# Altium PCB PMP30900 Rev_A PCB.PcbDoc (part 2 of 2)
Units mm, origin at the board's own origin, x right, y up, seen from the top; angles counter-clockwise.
Board outline 88.9 x 46.99 mm, 6 copper layers (Top Layer, Layer 2, Layer 3, Layer 4, Layer 5, Bottom Layer), stack 1.76 mm thick; 101 components, 54 nets, 324 pads, 212 vias.
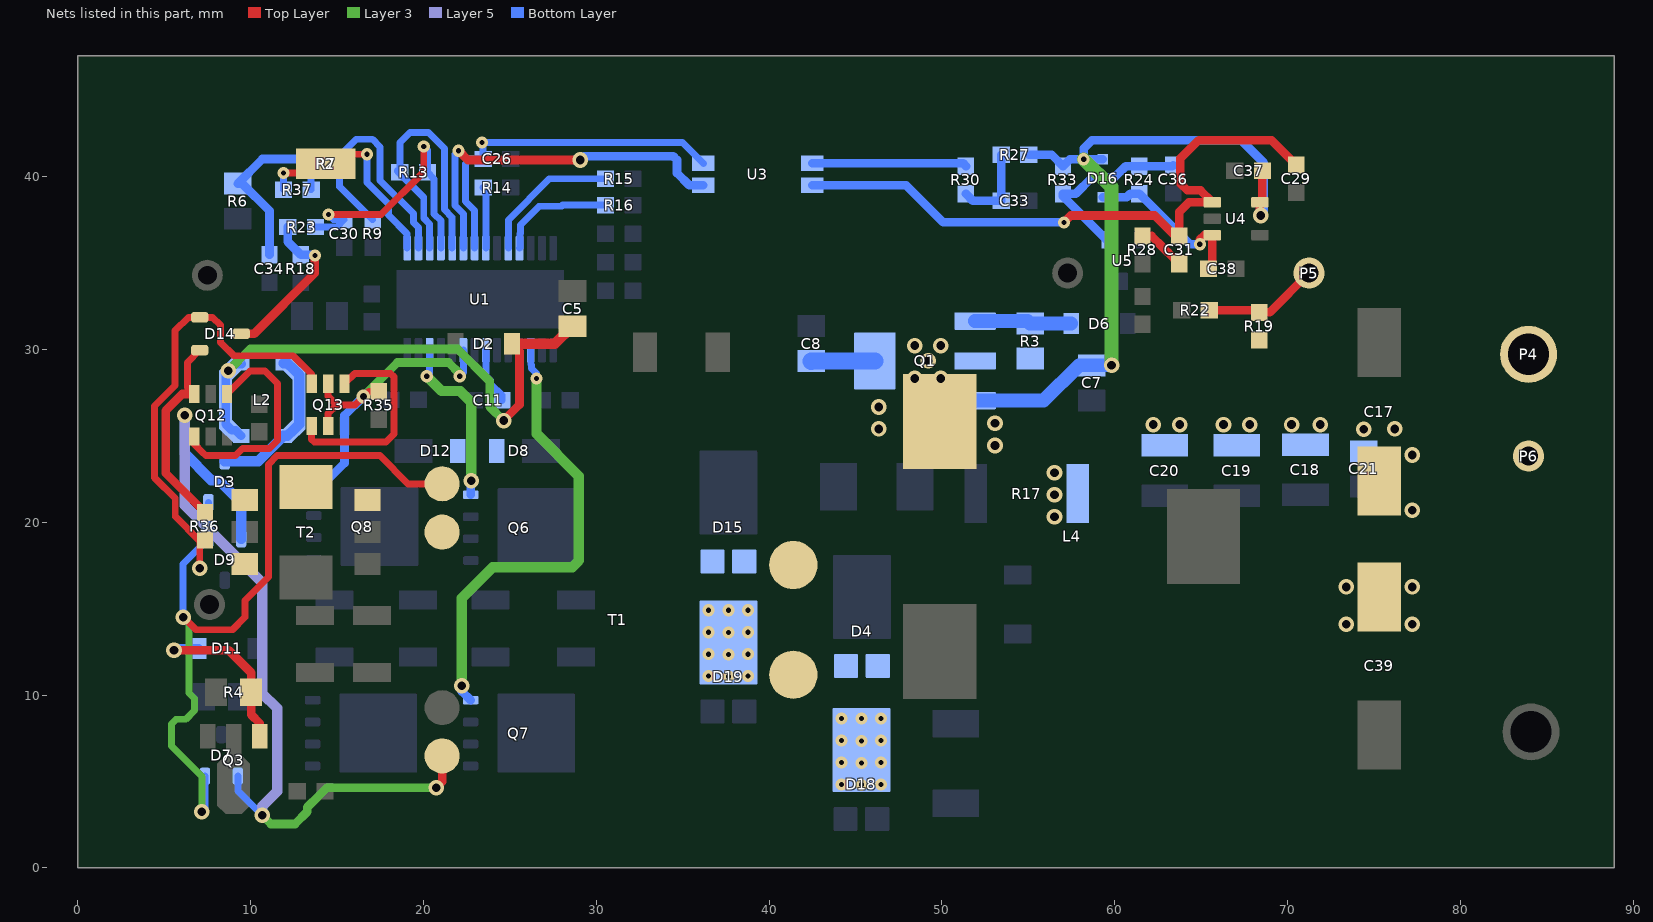
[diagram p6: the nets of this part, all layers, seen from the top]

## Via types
v1: diameter 0.7, hole 0.3, Top Layer to Bottom Layer, 68 vias
v2: diameter 0.9, hole 0.5, Top Layer to Bottom Layer, tented both sides, 30 vias
v3: diameter 0.7, hole 0.3, Top Layer to Bottom Layer, tented top, 25 vias
v4: diameter 0.9, hole 0.5, Top Layer to Bottom Layer, 22 vias
v5: diameter 0.9, hole 0.5, Top Layer to Bottom Layer, tented top, 20 vias
v6: diameter 0.7, hole 0.3, Top Layer to Bottom Layer, tented both sides, 18 vias
v7: diameter 0.6, hole 0.3, Top Layer to Bottom Layer, tented both sides, 18 vias
v8: diameter 0.7, hole 0.3, Top Layer to Bottom Layer, tented bottom, 5 vias
v9: diameter 0.6, hole 0.3, Top Layer to Bottom Layer, 3 vias
v10: diameter 0.9, hole 0.5, Top Layer to Bottom Layer, tented bottom, 2 vias
v11: diameter 0.8, hole 0.4, Top Layer to Bottom Layer, tented both sides, 1 vias

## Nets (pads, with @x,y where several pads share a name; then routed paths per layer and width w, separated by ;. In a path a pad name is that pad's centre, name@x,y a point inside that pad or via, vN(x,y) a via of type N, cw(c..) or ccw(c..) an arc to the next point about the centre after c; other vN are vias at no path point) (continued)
NetC29_2: C29.2 C31.2 U3.2 U4.1 | length 37.8
  Top Layer w0.5: v6(57.06,37.35) 57.46,37.75 62.32,37.75 63.505,36.565 C31.2@63.73,36.565 63.73,37.95 64.295,38.515 U4.1@65.648,38.515 64.961,39.201 64.205,39.201 63.797,39.61 63.797,41.055 64.853,42.111 69.073,42.111 C29.2@70.506,40.678
  Bottom Layer w0.5: U3.2@42.495,39.497 47.928,39.497 50.075,37.35 v6(57.06,37.35)
NetC30_1: C30.1 R13.1 R23.1 U1.4 | length 17.2
  Top Layer w0.4: v6(14.504,37.809) 17.556,37.809 20.017,40.27 v1(20.017,41.746)
  Bottom Layer w0.4: R23.1@13.754,37.084 14.986,37.084 C30.1@15.409,37.507 14.806,37.507 v6(14.504,37.809) ; v1(20.017,41.746) 20.231,41.532 R13.1@20.231,40.259 20.617,39.873 20.617,37.842 21.009,37.449 U1.4@21.009,35.859
NetC31_1: C31.1 R28.1 | length 2.8
  Top Layer w0.5: R28.1@61.606,36.565 62.13,36.565 62.805,35.89 62.805,35.878 63.069,35.615 63.08,35.615 C31.1@63.73,34.965
NetC33_1: C33.1 R27.1 R30.2 | length 4.9
  Bottom Layer w0.5: R30.2@51.39,39.007 51.79,38.608 C33.1@53.429,38.608 R27.1@53.429,41.275
NetC34_1: C34.1 R6.1 R7.2 R37.2 | length 11.5
  Bottom Layer w0.4: R37.2@13.5,39.243 13.5,40.695 R7.2@13.551,40.746
  Bottom Layer w0.5: C34.1@11.091,35.475 11.091,38.024 9.52,39.595 R6.1@9.256,39.595 10.682,41.021 13.174,41.021 R7.2@13.5,40.695
NetC36_1: C36.1 R24.2 R33.1 U5.1 | length 10.8
  Bottom Layer w0.5: U5.1@59.527,36.341 57.006,38.863 R33.1@57.006,39.007 57.741,39.007 58.683,39.95 59.977,39.95 60.635,40.607 R24.2@61.427,40.607 63.337,40.607 C36.1@63.385,40.655
NetC38_1: C38.1 D16.2 R24.1 U4.3 | length 10
  Top Layer w0.5: v6(64.923,36.09) 64.923,36.34 65.222,36.64 65.247,36.615 U4.3@65.648,36.615 65.648,34.897 C38.1@65.422,34.671
  Bottom Layer w0.5: D16.2@59.315,38.807 60.702,38.807 60.902,39.007 R24.1@61.427,39.007 64.345,36.09 v6(64.923,36.09)
NetD3_1: D3.1 D7.1 D9.2 T1.6 | length 50.6
  Top Layer w0.5: v4(20.733,4.644) 21.082,4.993 T1.6@21.082,6.477
  Layer 3 w0.5: v4(10.668,3.048) 11.176,2.54 12.573,2.54 13.282,3.249 13.282,3.506 13.978,4.202 13.982,4.202 14.424,4.644 v4(20.733,4.644)
  Layer 5 w0.6: v4(6.181,26.194) 6.181,20.994 10.682,16.493 10.682,10.083 11.536,9.229 11.536,4.445 10.668,3.577 v4(10.668,3.048)
  Bottom Layer w0.4: D7.1@9.257,5.312 9.257,4.459 v4(10.668,3.048)
  Bottom Layer w0.6: v4(6.181,26.194) 6.181,23.987 7.73,22.438 8.158,22.438 D3.1@9.456,21.14 D9.2@9.456,19.043
NetD3_2: D3.2 D7.2 D9.1 T1.1 | length 47
  Top Layer w0.4: v4(6.091,14.505) 6.101,14.505 6.826,13.779 8.941,13.779 9.667,14.505 9.667,15.478 11.033,16.844 11.033,23.351 11.536,23.855 17.485,23.855 19.115,22.225 T1.1@21.082,22.225
  Layer 3 w0.4: v4(6.091,14.505) 6.427,14.169 6.427,10.117 6.743,9.801 6.743,9.097 6.245,8.599 5.689,8.599 5.412,8.323 5.412,7.056 7.181,5.287 v4(7.181,3.249)
  Bottom Layer w0.4: v4(6.091,14.505) 6.091,17.578 6.206,17.692 6.206,17.695 6.704,18.193 6.706,18.193 D9.1@7.556,19.043 D3.2@7.556,21.14 ; v4(7.181,3.249) 7.357,3.425 D7.2@7.357,5.312
NetD3_3: D3.3 L2.2 | length 9.2
  Bottom Layer w0.6: D3.3@8.506,23.54 10.449,23.54 L2.2@11.905,24.996 12.131,24.996 L2.2@12.456,25.32 12.805,25.67 L2.2@12.805,27.096 12.805,28.522 L2.2@12.456,28.871 12.131,29.196 L2.2@11.905,29.196
NetD4_1: D4.1 D4.2 D18.3 T1.8
  other v1: 45.348,4.808 44.196,4.826 46.482,4.826 45.348,6.078 44.196,6.096 46.482,6.096 45.348,7.348 44.196,7.366 46.482,7.366 44.196,8.636 45.339,8.636 46.482,8.636
NetD6_1: D6.1 Q1.1 R3.1 | length 5.6
  Bottom Layer w0.8: Q1.1@51.922,31.637 54.963,31.637 R3.1@55.104,31.496 D6.1@57.481,31.496
NetD11_1: D11.1 Q3.1 R4.1 | length 10.4
  Top Layer w0.5: v4(5.565,12.594) 8.734,12.594 10.033,11.295 R4.1@10.033,10.16 10.033,8.862 10.517,8.378 Q3.1@10.517,7.615
  Bottom Layer w0.5: v4(5.565,12.594) 5.671,12.7 D11.1@6.999,12.7
NetD14_1: D14.1 Q13.6 R36.1 T2.3 | length 26
  Top Layer w0.4: v10(7.056,17.343) 7.056,18.926 5.639,20.343 5.639,21.367 4.43,22.575 4.43,26.723 5.629,27.923 5.629,31.092 6.397,31.859 D14.1@7.054,31.859 7.799,31.859 8.254,31.404 8.254,30.409 9.027,29.636 12.458,29.636 13.522,28.571 Q13.6@13.532,28.018
NetD14_2: D14.2 Q12.6 R36.2 T2.1 | length 11.9
  Top Layer w0.4: Q12.6@6.731,27.419 6.341,27.809 6.341,29.246 D14.2@7.054,29.959
  Top Layer w0.5: Q12.6@6.731,27.419 6.045,27.419 5.08,26.454 5.08,22.844 R36.2@7.357,20.568
NetD14_3: D14.3 R18.2 R23.2 | length 9.5
  Top Layer w0.5: D14.3@9.454,30.909 10.203,30.909 13.716,34.422 v8(13.716,35.433)
  Bottom Layer w0.5: R23.2@12.154,37.084 12.154,36.226 R18.2@12.902,35.478 13.671,35.478 v8(13.716,35.433)
NetD15_1: D15.1 D15.2 D19.3 T1.10
  other v1: 37.652,11.08 36.5,11.098 38.786,11.098 37.652,12.35 36.5,12.368 38.786,12.368 37.652,13.62 36.5,13.638 38.786,13.638 36.5,14.908 37.643,14.908 38.786,14.908
NetP2_1: P2.1 R37.1 U1.1 | length 12.6
  Top Layer w0.4: v6(11.9,40.204) 13.809,40.204 P2.1@14.351,40.746 14.898,41.293 v6(16.736,41.293)
  Bottom Layer w0.4: R37.1@11.9,39.243 v6(11.9,40.204) ; v6(16.736,41.293) 16.736,39.659 17.973,38.422 17.973,37.781 19.059,36.694 U1.1@19.059,35.859
NetP5_1: P5.1 R19.1 R22.2 | length 6.8
  Top Layer w0.5: R22.2@65.472,32.258 68.237,32.258 R19.1@68.351,32.144 68.974,32.144 P5.1@71.247,34.417
NetQ6_4: Q6.4 U1.26 | length 10.2
  Layer 3 w0.6: v6(20.193,28.448) 21.048,27.593 22.129,27.593 22.774,26.948 v2(22.774,22.399)
  Bottom Layer w0.4: v6(20.193,28.448) 20.359,28.614 U1.26@20.359,29.959
  Bottom Layer w0.5: Q6.4@22.743,21.59 22.743,22.368 v2(22.774,22.399)
NetQ7_4: Q7.4 U1.17 | length 27.1
  Layer 3 w0.6: v5(22.225,10.541) 22.225,15.611 22.479,15.865 22.482,15.865 23.039,16.421 23.039,16.425 24.013,17.399 28.611,17.399 28.996,17.784 28.996,22.672 26.543,25.125 v6(26.543,28.321)
  Bottom Layer w0.4: U1.17@26.209,29.959 26.209,29.203 26.234,29.178 26.234,29.122 26.262,29.095 26.259,29.095 26.259,28.899 26.284,28.874 ; 26.284,28.874 26.543,28.615 v6(26.543,28.321)
  Bottom Layer w0.5: v5(22.225,10.541) 22.225,10.211 Q7.4@22.731,9.705
NetQ8_4: Q8.4 Q13.2 Q13.5 R35.2 U1.23 | length 20.8
  Top Layer w0.4: Q13.2@14.482,25.568 14.482,26.293 14.982,26.793 ; Q13.5@14.482,28.018 14.482,27.293 14.982,26.793 ; R35.2@17.409,27.561 16.812,27.561 v11(16.52,27.269) 16.044,26.793 14.982,26.793
  Layer 3 w0.5: v11(16.52,27.269) 18.499,29.248 21.451,29.248 22.098,28.601 v6(22.098,28.448)
  Bottom Layer w0.4: v6(22.098,28.448) 22.309,28.659 U1.23@22.309,29.959
  Bottom Layer w0.5: Q8.4@13.657,21.653 15.432,23.428 15.432,26.181 v11(16.52,27.269)
NetQ12_1: Q12.1 Q12.4 | length 13
  Top Layer w0.4: Q12.1@6.731,24.969 6.731,24.533 6.981,24.283 6.981,24.278 7.215,24.044 7.22,24.044 7.409,23.855 9.131,23.855 9.541,24.265 10.833,24.265 10.84,24.258 11.09,24.258 11.553,24.72 11.553,28.038 10.831,28.76 10.078,28.76 10.076,28.759 9.971,28.759 Q12.4@8.631,27.419
NetQ13_1: Q13.1 Q13.4 | length 12.3
  Top Layer w0.4: Q13.1@13.532,25.568 13.532,24.793 13.682,24.643 17.831,24.643 18.295,25.107 18.295,28.42 18.105,28.609 16.023,28.609 Q13.4@15.432,28.018
NetR7_1: R7.1 R9.2 U1.2 | length 14.2
  Bottom Layer w0.4: R9.2@17.06,37.507 15.151,39.416 R7.1@15.151,40.746 15.151,41.181 16.134,42.164 17.039,42.164 17.493,41.709 17.493,39.781 19.417,37.857 19.417,37.345 19.709,37.052 U1.2@19.709,35.859
NetR13_2: R13.2 U1.3 U1.5 | length 16.2
  Bottom Layer w0.4: R13.2@18.697,40.546 R13.2@18.631,40.48 ; U1.3@20.359,35.859 20.359,37.251 20.017,37.593 20.017,38.799 18.504,40.312 18.504,40.353 R13.2@18.631,40.48 ; U1.5@21.659,35.859 21.659,37.648 21.217,38.09 21.217,41.622 20.294,42.545 19.21,42.545 18.631,41.966 R13.2@18.631,40.48
NetR14_2: R14.2 U1.8 | length 3.6
  Bottom Layer w0.4: R14.2@23.457,39.37 23.609,39.218 U1.8@23.609,35.859
NetR15_2: R15.2 U1.10 | length 8.2
  Bottom Layer w0.4: U1.10@24.909,35.859 24.909,37.491 27.296,39.878 R15.2@30.531,39.878
NetR16_2: R16.2 U1.11 | length 6.8
  Bottom Layer w0.4: U1.11@25.559,35.859 25.584,35.884 25.584,36.696 25.609,36.721 25.609,37.206 26.688,38.284 27.984,38.284 28.055,38.354 R16.2@30.531,38.354
NetR30_1: R30.1 U3.1 | length 9
  Bottom Layer w0.5: U3.1@42.495,40.767 51.231,40.767 R30.1@51.39,40.607
NetT1_2: T1.2 T2.6 T2.8
NetU1_6: U1.6 U3.3 | length 21.5
  Top Layer w0.5: v1(22.035,41.496) 22.569,40.962 v4(29.083,40.962)
  Bottom Layer w0.4: v1(22.035,41.496) 21.832,41.293 21.832,38.324 22.309,37.847 U1.6@22.309,35.859
  Bottom Layer w0.5: v4(29.083,40.962) 29.302,41.181 34.456,41.181 34.671,40.966 34.671,40.204 35.378,39.497 U3.3@36.195,39.497
SBIAS: C7.1 C37.2 D16.1 Q1.3 R27.2 R33.2 U4.5 | length 43.6
  Top Layer w0.5: v2(68.445,37.75) 68.398,37.797 U4.5@68.398,38.515 68.546,38.663 C37.2@68.546,40.33
  Layer 3 w0.8: v6(58.203,41.007) 59.817,39.394 v4(59.817,29.083)
  Bottom Layer w0.5: R27.2@55.029,41.275 56.338,41.275 R33.2@57.006,40.607 57.406,41.007 v6(58.203,41.007) ; D16.1@59.315,41.007 v6(58.203,41.007) ; v2(68.445,37.75) 68.621,37.927 68.621,40.805 67.316,42.111 58.683,42.111 58.203,41.631 v6(58.203,41.007)
  Bottom Layer w0.8: Q1.3@51.922,27.037 55.89,27.037 57.936,29.083 C7.1@58.674,29.083 v4(59.817,29.083)
VCC: C5.1 C11.1 D2.1 D8.2 D12.2 L2.1 U1.21 | length 36
  Top Layer w0.5: v4(24.638,25.886) 25.559,26.807 25.559,29.892 D2.1@25.124,30.327 D2.1@25.124,30.3
  Top Layer w0.6: D2.1@25.124,30.327 27.61,30.327 C5.1@28.626,31.343
  Layer 3 w0.5: v4(8.706,28.76) 9.968,30.022 21.968,30.022 23.838,28.152 23.838,26.686 v4(24.638,25.886)
  Bottom Layer w0.4: U1.21@23.609,29.959 23.609,28.473 23.888,28.194 23.888,28.01 24.549,27.349 C11.1@24.549,27.051
  Bottom Layer w0.5: v4(8.706,28.76) 8.555,28.61 L2.1@8.555,27.096 8.555,25.67 L2.1@8.904,25.32 9.131,25.32 L2.1@9.455,24.996 ; L2.1@9.104,29.159 9.492,29.159 L2.1@9.455,29.196
VOUT: C8.1 C17.1 C18.1 C19.1 C20.1 C21.1 C39.1 L4.1 P4.1 P6.1 Q1.2 Q1.4 R3.2 R17.2 R19.2 | length 3.7
  Bottom Layer w1: C8.1@42.439,29.321 42.455,29.337 Q1.4@46.122,29.337
  other v2: 73.406,14.097 77.216,14.097 73.406,16.256 77.216,16.256 56.515,20.32 56.515,21.59 56.515,22.86 53.071,24.442 46.355,25.4 62.23,25.654 63.754,25.654 66.294,25.654 67.818,25.654 70.231,25.654 71.882,25.654 53.071,25.737 46.355,26.67 48.438,28.321 49.943,28.321 49.197,29.337 48.438,30.224 49.943,30.224
  other v4: 77.216,20.701 77.216,23.892 76.2,25.4
  other v5: 74.413,25.38
VREF: C26.1 U1.7 U3.4 | length 20.5
  Bottom Layer w0.4: U1.7@22.959,35.859 22.959,38.045 22.432,38.573 22.432,40.746 22.707,41.021 C26.1@23.457,41.021 23.457,41.898 v6(23.389,41.966) 34.996,41.966 U3.4@36.195,40.767
pads on no net: L4.3 Q6.9@25.158,18.235 Q6.9@25.158,19.685 Q6.9@25.158,21.135 Q6.9@26.088,19.685 Q6.9@26.938,18.235 Q6.9@26.938,19.685 Q6.9@26.938,21.135 Q7.9@25.146,6.35 Q7.9@25.146,7.8 Q7.9@25.146,9.25 Q7.9@26.076,7.8 Q7.9@26.926,6.35 Q7.9@26.926,7.8 Q7.9@26.926,9.25 Q8.9@16.072,18.298 Q8.9@16.072,19.748 Q8.9@16.072,21.198 Q8.9@17.002,19.748 Q8.9@17.852,18.298 Q8.9@17.852,19.748 Q8.9@17.852,21.198 Q9.9@16.002,6.35 Q9.9@16.002,7.8 Q9.9@16.002,9.25 Q9.9@16.932,7.8 Q9.9@17.782,6.35 Q9.9@17.782,7.8 Q9.9@17.782,9.25 T2.2 U1.19 U1.24 U1.29@23.284,32.909 U5.3
copper on no net:
  other v6: 10.389,28.01
  other v8: 18.161,35.306 18.161,36.195

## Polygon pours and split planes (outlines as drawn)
VOUT on Bottom Layer "BOTTOM_LAYER_VOUT_P055" (solid, remove dead copper, pour order 55): 64.235,23.495 60.026,23.495 59.561,23.03 59.561,19.814 59.134,19.387 56.712,19.387 55.779,20.32 55.779,25.275 56.594,26.089 64.235,26.089
VOUT on Bottom Layer "BOTTOM_LAYER_VOUT_P054" (solid, remove dead copper, pour order 54): 61.264,23.495 82.099,23.495 83.248,22.347 85.141,22.347 85.141,27.833 79.357,33.617 64.89,33.617 61.22,29.947
IGND on Bottom Layer "BOTTOM_LAYER_IGND_P053" (solid, remove dead copper, pour order 53): 41.37,30.657 43.287,30.657 43.455,30.826 43.455,32.84 42.989,33.306 41.667,33.306 41.37,33.009
IGND on Bottom Layer "BOTTOM_LAYER_IGND_P052" (solid, remove dead copper, pour order 52): 35.941,9.832 35.941,4.572 39.37,1.143 85.598,1.143 88.011,3.556 88.011,5.207 84.582,5.207 84.09,5.699 84.09,10.263 84.622,10.795 84.622,19.899 81.788,22.733 60.268,22.733 60.268,19.77 59.04,18.542 56.991,18.542 56.515,18.066 56.515,15.256 55.779,14.52 53.321,14.52 52.848,14.047 52.848,6.951 52.247,6.35 49.456,6.35 46.878,3.771 42.865,3.771 39.282,7.354 39.282,9.868
IGND on Bottom Layer "BOTTOM_LAYER_IGND_P051" (solid, remove dead copper, pour order 51): 83.566,6.223 86.741,6.223 88.011,7.493 88.011,40.353 83.868,44.496 67.538,44.496 67.538,43.646 70.431,40.753 78.3,40.753 86.07,32.983 86.07,9.913 85.678,9.521 83.566,9.527
IGND on Bottom Layer "BOTTOM_LAYER_IGND_P047" (solid, remove dead copper, pour order 47): 40.986,44.496 68.171,44.496 71.862,40.805 71.862,35.032 70.929,34.099 44.384,34.099 41.033,37.449
VOUT on Bottom Layer "BOTTOM_LAYER_VOUT_P046" (solid, remove dead copper, pour order 46): 58.771,19.387 56.712,19.387 55.779,20.32 55.779,22.136 54.003,23.912 52.679,23.912 52.293,24.298 47.06,24.298 44.45,26.908 44.45,31.637 49.457,31.637 50.797,30.297 55.813,30.297 56.12,29.99 56.12,28.891 55.829,28.6 50.964,28.6 50.165,27.801 50.165,26.345 50.42,26.089 56.594,26.089 58.771,23.912
NetC23_1 on Bottom Layer "BOTTOM_LAYER_NETC23_1_P045" (solid, remove dead copper, pour order 45): 47.402,20.617 50.164,20.617 52.679,18.102 52.679,16.363 55.283,16.363 55.329,16.317 55.329,20.685 52.507,23.506 47.378,23.506
NetC16_2 on Bottom Layer "BOTTOM_LAYER_NETC16_2_P043" (solid, remove dead copper, pour order 43): 52.247,7.348 49.453,7.348 49.117,7.684 49.117,11.716 51.777,11.716 52.247,11.246
NetC16_1 on Bottom Layer "BOTTOM_LAYER_NETC16_1_P042" (solid, remove dead copper, pour order 42): 35.917,19.207 42.784,19.207 43.656,18.335 43.656,13.237 43.721,13.172 51.156,13.172 51.192,13.208 51.192,18.43 49.657,19.965 47.38,19.965 46.728,20.617 46.728,23.692 46.115,24.305 35.941,24.305
NetD15_1 on Bottom Layer "BOTTOM_LAYER_NETD15_1_P040" (solid, remove dead copper, pour order 40): 35.941,18.542 39.415,18.542 39.718,18.9 42.062,18.9 42.865,18.098 42.865,13.462 42.349,12.946 39.718,12.946 39.37,12.598 39.37,10.627 39.306,10.563 35.941,10.563
NetD4_1 on Bottom Layer "BOTTOM_LAYER_NETD4_1_P037" (solid, remove dead copper, pour order 37): 47.069,4.381 43.086,4.381 40.005,7.462 40.005,12.274 40.304,12.573 46.99,12.573
NetC9_1 on Bottom Layer "BOTTOM_LAYER_NETC9_1_P026" (solid, remove dead copper, pour order 26): 11.308,2.794 6.77,2.794 5.412,4.152 5.412,9.96 7.184,9.96 8.707,8.437 11.317,8.437
GND on Bottom Layer "BOTTOM_LAYER_GND_P025" (solid, remove dead copper, pour order 25): 14.078,5.506 15.542,4.042 15.542,2.794 14.169,2.794 11.675,5.288 11.675,8.62 11.995,8.941 12.89,8.941 13.068,8.763 14.097,8.763
NetC15_1 on Bottom Layer "BOTTOM_LAYER_NETC15_1_P024" (solid, remove dead copper, pour order 24): 23.389,17.174 22.295,16.079 21.853,16.079 21.619,16.314 21.619,16.943 21.104,17.458 15.237,17.458 15.095,17.6 15.095,21.986 15.357,22.248 20.658,22.248 22.144,20.761 23.195,20.761 23.389,20.568
NetC12_1 on Bottom Layer "BOTTOM_LAYER_NETC12_1_P023" (solid, remove dead copper, pour order 23): 22.987,4.572 21.844,4.572 21.082,5.334 15.384,5.334 15.04,5.678 15.04,10.189 15.15,10.3 20.958,10.3 22.491,8.767 23.226,8.767 23.226,4.811
GND on Bottom Layer "BOTTOM_LAYER_GND_P011" (solid, remove dead copper, pour order 11): 17.535,13.462 19.042,14.969 21.085,14.969 21.282,15.167 21.282,16.643 21.11,16.815 14.835,16.815 14.3,17.35 14.3,20.643 11.643,20.643 10.768,19.768 10.768,19.03 9.956,18.218 9.132,18.218 8.082,17.168 8.082,9.569 8.507,9.144 10.186,9.144 10.186,11.674 11.974,13.462
NetC1_1 on Bottom Layer "BOTTOM_LAYER_NETC1_1_P009" (solid, remove dead copper, pour order 9): 11.495,10.669 18.642,10.669 19.328,11.355 22.124,11.355 24.259,9.219 24.259,3.873 24.576,3.557 29.474,3.557 29.967,4.05 29.967,20.914 28.834,22.048 24.259,22.048 24.259,17.645 21.369,14.755 19.508,14.755 17.708,12.955 12.221,12.955 11.501,12.234
GND on Bottom Layer "BOTTOM_LAYER_GND_P004" (solid, remove dead copper, pour order 4): 21.217,31.22 19.498,31.22 18.134,32.584 16.692,32.584 16.002,33.274 10.414,33.274 10.287,33.401 10.287,34.596 10.366,34.675 13.938,34.675 14.605,35.342 14.605,36.449 17.653,36.449
NetC15_2 on Bottom Layer "BOTTOM_LAYER_NETC15_2_P003" (solid, remove dead copper, pour order 3): 19.05,27.686 19.05,26.289 18.161,25.4 18.161,23.368 18.288,23.241 20.431,23.241 20.685,23.495 20.701,23.495 20.701,27.432 20.447,27.686
VCC on Bottom Layer "BOTTOM_LAYER_VCC_P002" (solid, remove dead copper, pour order 2): 23.888,27.526 23.888,26.344 23.487,25.943 22.26,25.943 21.463,25.146 21.463,23.464 21.537,23.39 24.914,23.39 25.146,23.622 25.146,27.686 24.048,27.686
NetC12_2 on Bottom Layer "BOTTOM_LAYER_NETC12_2_P001" (solid, remove dead copper, pour order 1): 26.335,27.571 25.654,26.89 25.654,23.568 25.682,23.54 25.654,23.512 25.654,23.241 27.786,23.241 28.084,23.54 28.084,25.616 27.432,26.269 27.432,27.559
GND on Bottom Layer "BOTTOM_LAYER_GND_P000" (solid, remove dead copper, pour order 0): 18.484,34.577 27.777,34.577 29.678,32.676 31.076,32.676 31.331,32.931 31.331,40.353 31.581,40.603 32.856,40.603 33.147,40.312 33.147,32.139 32.206,31.198 32.162,31.242 18.484,31.242
IGND on Top Layer "TOP_LAYER_IGND_P006" (solid, remove dead copper, pour order 6): 77.765,5.039 72.915,5.039 72.915,10.201 77.765,10.201
IGND on Top Layer "TOP_LAYER_IGND_P007" (solid, remove dead copper, pour order 7): 72.917,27.94 77.724,27.94 77.724,33.351 72.867,33.351
NetC16_1 on Top Layer "TOP_LAYER_NETC16_1_P008" (solid, remove dead copper, pour order 8): 47.334,13.172 47.661,12.845 47.661,9.791 52.074,9.791 52.115,9.832 52.115,21.433 50.876,22.672 46.974,22.672 45.094,24.553 36.195,24.553 35.845,24.203 35.845,19.99 36.488,19.347 43.568,19.347 43.568,13.574 43.971,13.172
NetD15_1 on Top Layer "TOP_LAYER_NETD15_1_P012" (solid, remove dead copper, pour order 12): 35.917,18.51 39.391,18.51 39.694,18.868 42.038,18.868 42.841,18.066 42.841,13.43 42.325,12.914 39.694,12.914 39.346,12.566 39.346,10.595 39.282,10.531 35.917,10.531
NetD4_1 on Top Layer "TOP_LAYER_NETD4_1_P013" (solid, remove dead copper, pour order 13): 47.078,4.389 43.095,4.389 40.014,7.47 40.014,12.282 40.313,12.581 46.999,12.581
GND on Top Layer "TOP_LAYER_GND_P049" (solid, remove dead copper, pour order 49): 29.678,32.676 25.89,32.676 25.682,32.884 25.682,34.347 26.006,34.671 29.464,34.671 29.718,34.417
IGND on Top Layer "TOP_LAYER_IGND_P048" (solid, remove dead copper, pour order 48): 36.291,28.605 38.933,28.605 38.933,30.989 36.291,30.989
GND on Top Layer "TOP_LAYER_GND_P044" (solid, remove dead copper, pour order 44): 33.497,28.603 30.825,28.603 30.825,31.037 33.497,31.037
VOUT on Top Layer "TOP_LAYER_VOUT_P041" (solid, remove dead copper, pour order 41): 41.827,34.257 83.345,34.257 88.011,29.591 88.011,3.556 85.598,1.143 41.91,1.143
NetD14_2 on Top Layer "TOP_LAYER_NETD14_2_P039" (solid, remove dead copper, pour order 39): 6.632,20.039 8.131,20.039 8.659,20.568 10.414,20.568 10.414,21.844 10.093,22.165 6.925,22.165 6.604,21.844
NetD14_1 on Top Layer "TOP_LAYER_NETD14_1_P036" (solid, remove dead copper, pour order 36): 10.414,16.895 6.671,16.895 6.223,17.343 6.223,19.319 6.427,19.523 8.082,19.523 8.082,18.767 8.602,18.247 10.414,18.247
GND on Top Layer "TOP_LAYER_GND_P028" (solid, remove dead copper, pour order 28): 18.11,13.855 17.718,13.462 12.583,13.462 12.316,13.729 12.316,14.93 12.626,15.24 18.034,15.24 18.034,15.232 18.11,15.156
NetT1_2 on Top Layer "TOP_LAYER_NETT1_2_P014" (solid, remove dead copper, pour order 14): 21.832,18.478 19.711,18.478 17.622,20.568 11.553,20.568 11.166,20.955 11.166,23.145 11.389,23.368 16.764,23.368 18.952,21.18 19.812,21.18 20.535,20.457 21.491,20.457 22.14,19.808 22.14,19.054
NetC15_1 on Top Layer "TOP_LAYER_NETC15_1_P027" (solid, remove dead copper, pour order 27): 11.341,15.319 21.542,15.319 23.389,17.166 23.389,20.568 12.65,20.568 11.341,19.259
NetC9_1 on Top Layer "TOP_LAYER_NETC9_1_P022" (solid, remove dead copper, pour order 22): 10.768,2.794 7.189,2.794 6.681,3.302 6.681,5.867 7.291,6.477 10.73,6.477 11.317,5.89 11.317,3.398
NetC1_1 on Top Layer "TOP_LAYER_NETC1_1_P021" (solid, remove dead copper, pour order 21): 11.557,10.668 18.705,10.668 19.391,11.354 22.186,11.354 23.876,9.664 23.876,4.318 24.638,3.556 29.536,3.556 29.967,3.987 29.967,20.976 28.896,22.047 24.128,22.047 23.768,21.687 23.768,17.091 21.431,14.754 19.57,14.754 17.77,12.954 12.283,12.954 11.563,12.234
NetC12_1 on Top Layer "TOP_LAYER_NETC12_1_P020" (solid, remove dead copper, pour order 20): 15.113,5.126 14.715,5.524 12.553,5.524 11.95,6.127 11.95,9.41 12.704,10.164 19.053,10.164 19.812,10.923 21.771,10.923 23.326,9.368 23.326,4.841 22.041,3.556 16.683,3.556
IGND on Layer 2 "LAYER_2_IGND_P057" (solid, remove dead copper, pour order 57): 85.59,1.147 39.362,1.147 35.933,4.576 35.933,28.187 36.187,28.441 36.187,31.019 40.978,35.809 40.978,44.5 85.29,44.5 88.003,41.787 88.003,3.56
GND on Layer 2 "LAYER_2_GND_P030" (solid, remove dead copper, pour order 30): 3.81,1.27 27.935,1.27 30.531,3.866 30.531,24.224 33.528,27.221 33.528,32.694 37.431,36.597 37.431,44.45 3.81,44.45
IGND on Layer 5 "LAYER_5_IGND_P056" (solid, remove dead copper, pour order 56): 85.598,1.143 39.37,1.143 35.941,4.572 35.941,28.183 36.195,28.437 36.195,31.015 40.986,35.806 40.986,44.496 85.298,44.496 88.011,41.783 88.011,3.556
NetC9_1 on Layer 5 "LAYER_5_NETC9_1_P033" (solid, remove dead copper, pour order 33): 3.81,1.27 9.097,1.27 11.536,3.71 11.536,9.229 10.682,10.083 10.682,16.493 7.341,19.834 3.778,19.834
GND on Layer 5 "LAYER_5_GND_P032" (solid, remove dead copper, pour order 32): 10.965,1.316 12.12,2.472 12.12,9.647 11.176,10.592 11.176,15.999 6.997,20.178 3.778,20.178 3.778,44.496 37.431,44.496 37.431,36.675 33.496,32.74 33.496,27.708 30.499,24.711 30.499,3.912 27.903,1.316
VOUT on Layer 4 "LAYER_4_VOUT_P058" (solid, remove dead copper, pour order 58): 85.565,1.147 39.337,1.147 35.908,4.576 35.908,28.187 36.162,28.441 36.162,31.019 40.953,35.809 40.953,44.5 85.265,44.5 87.978,41.787 87.978,3.56
NetC1_1 on Layer 4 "LAYER_4_NETC1_1_P035" (solid, remove dead copper, pour order 35): 12.221,1.28 27.945,1.28 30.531,3.866 30.531,24.591 33.528,27.588 33.528,32.694 37.465,36.631 37.465,44.496 3.814,44.496 3.778,44.46 3.778,21.129 4.43,20.477 11.121,20.477 12.167,19.431
NetC9_1 on Layer 4 "LAYER_4_NETC9_1_P034" (solid, remove dead copper, pour order 34): 3.81,1.316 9.097,1.316 11.536,3.756 11.536,9.275 11.536,19.365 11.021,19.881 3.778,19.881
VOUT on Layer 3 "LAYER_3_VOUT_P059" (solid, remove dead copper, pour order 59): 85.59,1.147 39.362,1.147 35.933,4.576 35.933,28.187 36.187,28.441 36.187,31.019 40.978,35.809 40.978,44.5 85.29,44.5 88.003,41.787 88.003,3.56
GND on Layer 3 "LAYER_3_GND_P031" (solid, remove dead copper, pour order 31): 3.778,1.28 27.903,1.28 30.499,3.876 30.499,24.218 33.496,27.215 33.496,32.704 37.431,36.639 37.431,44.46 3.778,44.46

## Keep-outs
Keep-Out Layer:
  text ".Layer_Name" at 14.656,-21.806 h1.52

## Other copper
Top Layer:
  text ".Layer_Name" at 14.656,-21.806 h1.52
Bottom Layer:
  text ".Layer_Name" at 14.656,-21.806 h1.52

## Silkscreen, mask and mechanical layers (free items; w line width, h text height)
Top Overlay:
  text "NWA" at 73.142,35.621 h1.5 r45
  text "VIN" at 5.18,32.576 h1.5 r90
  text "VOUT" at 81.445,32.383 h1.5
  text "GND" at 4.331,13.225 h1.5 r90
  text "IGND" at 81.465,3.632 h1.5
  text "'.PRJ_Number'.PCB_Rev" at 49.554,2.694 h2
  text ".Layer_Name" at 14.656,-21.806 h1.52
Bottom Overlay:
  text ".Layer_Name" at 14.656,-21.806 h1.52
Top Paste:
  text ".Layer_Name" at 14.656,-21.806 h1.52
Bottom Paste:
  text ".Layer_Name" at 14.656,-21.806 h1.52
Top Solder:
  text ".Layer_Name" at 14.656,-21.806 h1.52
  text ".Layer_Name" at 14.656,-21.806 h1.52
Bottom Solder:
  text "'.PRJ_Number'.PCB_Rev" at 77.417,1.905 h2
  text ".Layer_Name" at 14.656,-21.806 h1.52
Drill Guide:
  text ".Layer_Name" at 14.656,-21.806 h1.52
M1 Board Outline:
  the board outline again, w0.254
  text ".Layer_Name" at 14.656,-21.806 h1.52
M2 Board Dimensions:
  rectangle: 0,-6.985 3.175,-3.81
  rectangle: 3.175,-10.16 12.7,-6.985
  lines w0.178: 0,-6.985 25.4,-6.985 ; 3.175,-10.16 3.175,-3.81 ; 6.35,-10.16 6.35,-3.81 ; 12.7,-10.16 12.7,-3.81 ; 19.05,-10.16 19.05,-3.81 ; 0,-10.16 25.4,-10.16 25.4,-3.81 0,-3.81 0,-10.16
  text ".Layer_Name" at 14.656,-21.806 h1.52
M3 3D STEP Top:
  text ".Layer_Name" at 14.656,-21.806 h1.52
M4 3D STEP Bottom:
  text ".Layer_Name" at 14.656,-21.806 h1.52
M5 Assembly Top:
  lines w0.15: 47.873,7.925 47.873,30.425 67.073,30.425 67.073,7.925 47.873,7.925
  lines w0.254: -7.417,-23.626 160.223,-23.626 ; -7.417,-18.462 160.274,-18.462 ; -7.417,-13.297 -7.417,-28.791 94.31,-28.791 160.274,-28.791 160.274,-13.297 -7.404,-13.297 -7.404,-28.791 32.614,-28.791 ; 55.194,-28.791 55.194,-13.297 ; 87.376,-18.462 87.376,-13.297 ; 108.712,-18.462 108.712,-13.297 ; 124.511,-28.956 124.511,-23.804
  text "COMPONENTS MARKED 'DNP' SHOULD NOT BE POPULATED." at 29.299,-8.09 h1.52
  text "ASSEMBLY VARIANT:" at 29.286,-11.024 h1.52
  text ".VariantName" at 55.601,-11.024 h1.52
  text "PCB VIEWED FROM TOP SIDE" at -5.804,-16.654 h1.52
  text "BOARD #:" at 57.099,-16.654 h1.52
  text ".PRJ_Number" at 70.955,-16.654 h1.52
  text "REV:" at 92.405,-16.654 h1.52
  text ".PCB_Rev" at 99.809,-16.654 h1.52
  text "SVN REV:" at 113.69,-16.654 h1.52
  text ".VersionControl_RevNumber" at 126.543,-16.654 h1.52
  text "TID #:" at 57.099,-21.819 h1.52
  text ".TID" at 70.955,-21.819 h1.52
  text "PLOT NAME =" at -5.804,-27.034 h1.52
  text ".plot_File_Name" at 14.656,-27.034 h1.52
  text "GENERATED    :" at 57.15,-27.034 h1.52
  text ".Print_Date" at 79.235,-27.034 h1.52
  text ".Print_Time" at 97.752,-27.034 h1.52
  text "TEXAS INSTRUMENTS" at 129.87,-27.034 h1.52
M6 Assembly Bottom:
  lines w0.254: -7.429,-18.474 160.261,-18.474 ; -7.379,-23.639 160.261,-23.639 ; 28.334,-28.969 28.334,-23.817 ; 44.133,-18.474 44.133,-13.31 ; 65.468,-18.474 65.468,-13.31 ; 97.65,-28.804 97.65,-13.31 ; 120.231,-28.804 160.249,-28.804 160.249,-13.31 -7.429,-13.31 -7.429,-28.804 58.534,-28.804 160.261,-28.804 160.261,-13.31
  text "COMPONENTS MARKED 'DNP' SHOULD NOT BE POPULATED." at 154.991,-8.077 h1.52
  text ".VariantName" at 128.473,-11.024 h1.52
  text "ASSEMBLY VARIANT:" at 154.864,-11.024 h1.52
  text ".VersionControl_RevNumber" at 26.302,-16.667 h1.52
  text "SVN REV:" at 39.154,-16.667 h1.52
  text ".PCB_Rev" at 53.035,-16.667 h1.52
  text "REV:" at 60.439,-16.667 h1.52
  text ".PRJ_Number" at 81.89,-16.667 h1.52
  text "BOARD #:" at 95.745,-16.667 h1.52
  text "PCB VIEWED FROM BOTTOM SIDE" at 158.648,-16.667 h1.52
  text ".TID" at 81.89,-21.831 h1.52
  text "TID #:" at 95.745,-21.831 h1.52
  text "TEXAS INSTRUMENTS" at 22.974,-27.047 h1.52
  text ".Print_Time" at 55.093,-27.047 h1.52
  text ".Print_Date" at 73.609,-27.047 h1.52
  text "GENERATED    :" at 95.694,-27.047 h1.52
  text ".plot_File_Name" at 138.189,-27.047 h1.52
  text "PLOT NAME =" at 158.648,-27.047 h1.52
M9 Title Sheet:
  drawing of 57 lines, arcs and shapes, not listed
  text "1" at 18.792,204.127 h1.78
  text "2" at 82.182,204.127 h1.78
  text "3" at 145.411,204.127 h1.78
  text "4" at 209.08,204.127 h1.78
  text "5" at 272.555,204.127 h1.78
  text "6" at 336.182,204.127 h1.78
  text "A" at -10.579,175.095 h1.78
  text "A" at 365.341,175.095 h1.78
  text "B" at -10.579,114.643 h1.78
  text "B" at 365.341,114.643 h1.78
  text "C" at -10.579,54.318 h1.78
  text "C" at 365.341,54.318 h1.78
  text "PROJECT TITLE:" at 288.125,7.048 h1.14
  text ".PRJ_Title" at 289.395,3.662 h1.78
  text "DESIGNED FOR:" at 288.125,-0.597 h1.14
  text ".PRJ_Customer" at 289.395,-4.153 h1.78
  text "D" at -10.579,-5.88 h1.78
  text "D" at 365.341,-5.88 h1.78
  text "FILE NAME:" at 288.125,-8.217 h1.14
  text ".PCB_File_Name_No_Path" at 289.395,-11.265 h1.78
  text "Texas Instruments (TI) and/or its licensors do not warrant the accuracy or completeness of this specification" at 161.9,-15.376 h1.14
  text "ENGINEER:" at 288.125,-15.583 h1.14
  text "LAYOUT BY:" at 326.352,-15.583 h1.14
  text "or any information contained therein. TI and/or its licensors do not warrant that this design will meet" at 160.757,-18.237 h1.14
  text ".PRJ_Engineer" at 289.395,-19.52 h1.78
  text ".PCB_Layout" at 327.635,-19.52 h1.78
  text "the specifications, will be suitable for your application or fit for any particular purpose, or will operate in" at 160.757,-21.099 h1.14
  text ".Layer_Name" at 14.656,-21.806 h1.52
  text "ALTIUM DESIGNER VERSION:" at 326.352,-23.457 h1.14
  text "an implementation. TI and/or its licensors do not warrant that the design is production worthy. You should" at 160.757,-23.961 h1.14
  text "completely validate and test your design implementation to confirm the system functionality for your application." at 161.9,-26.822 h1.14
  text ".print_Scale" at 289.395,-26.843 h1.78
  text ".Application_BuildNumber" at 327.635,-26.843 h1.78
  text "1" at 18.792,-32.093 h1.78
  text "2" at 82.182,-32.093 h1.78
  text "3" at 145.411,-32.093 h1.78
  text "4" at 209.08,-32.093 h1.78
  text "5" at 272.555,-32.093 h1.78
  text "6" at 336.182,-32.093 h1.78
M10 Fab Notes:
  drawing of 189 lines, arcs and shapes, not listed
  text "DESIGN INFORMATION" at 314.503,161.447 h1.52
  text "MIN. TRACK WIDTH:" at 298.131,158.091 h1.52
  text "8" at 325.976,158.091 h1.52
  text "MIL" at 329.907,158.091 h1.52
  text "MIN. CLEARANCE:" at 298.131,154.938 h1.52
  text "0.2" at 324.452,154.938 h1.52
  text "mm" at 329.907,154.938 h1.52
  text "MIN. VIA PAD SIZE:" at 298.131,151.785 h1.52
  text "24" at 325.214,151.785 h1.52
  text "MIL" at 329.907,151.785 h1.52
  text "0.05mm (2MIL)" at 315.784,148.486 h1.52
  text "MINIMUM ANNULAR RING" at 289.769,148.277 h1.52
  text "EXTERNAL" at 333.768,148.277 h1.52
  text "PER" at 294.849,145.48 h1.52
  text "IPC-D-275 CLASS 2 LEVEL C" at 300.437,145.48 h1.52
  text "MIL, HOLES" at 338.238,142.928 h1.52
  text "+/-" at 328.27,142.709 h1.52
  text "+/-" at 349.961,142.709 h1.52
  text "REGISTRATION TOLERANCES:" at 289.769,142.682 h1.52
  text "METAL" at 320.243,142.682 h1.52
  text "5" at 334.879,142.683 h1.52
  text "3" at 356.037,142.683 h1.52
  text "MIL" at 358.99,142.682 h1.52
  text "HOLE SIZE TOLERANCE (UNLESS OTHERWISE SPECIFIED):" at 289.769,140.185 h1.52
  text "+/-" at 349.961,140.112 h1.52
  text "3" at 356.037,140.085 h1.52
  text "MIL" at 358.99,140.085 h1.52
  text "MATERIAL:" at 287.87,136.589 h1.52
  text "FR-4 High Tg" at 312.926,133.324 h1.52
  text "X" at 309.257,133.122 h1.52
  text "FR-408" at 298.563,133.007 h1.52
  text "OTHER" at 336.358,133.007 h1.52
  text "62 MIL (1.6mm) +/-10%" at 306.694,129.374 h1.52
  text "X" at 303.643,129.312 h1.52
  text "THICKNESS:" at 289.769,129.165 h1.52
  text "OTHER" at 339.33,129.165 h1.52
  text "TOLERANCE:" at 289.769,125.652 h1.52
  text "X" at 311.314,125.652 h1.52
  text "ANSI IPC-6012 TYPE 3 CLASS 2" at 315.836,125.652 h1.52
  text "OTHER +/-" at 315.835,121.989 h1.52
  text "BOW & TWIST:" at 289.769,118.302 h1.52
  text "X" at 311.314,118.302 h1.52
  text "ANSI IPC-6012 TYPE 3 CLASS 2" at 315.836,118.302 h1.52
  text "OTHER +/-" at 315.835,114.576 h1.52
  text "DRILLING:" at 287.87,111.258 h1.52
  text "NC_DRILL FILES" at 332.599,108.586 h1.52
  text "REFERENCE:" at 289.769,108.486 h1.52
  text "X" at 306.463,108.484 h1.52
  text "AS SHOWN" at 310.984,108.486 h1.52
  text "X" at 329.348,108.486 h1.52
  text "OTHER" at 340.168,104.873 h1.52
  text "PTH COPPER THICKNESS:" at 289.761,104.783 h1.52
  text "X" at 318.697,104.783 h1.52
  text "20-30 um" at 321.948,104.783 h1.52
  text "BOARD FINISH:" at 287.87,101.034 h1.52
  text "SILKSCREEN:" at 291.812,98.237 h1.52
  text "X" at 316.14,98.237 h1.52
  text "TOP" at 319.112,98.237 h1.52
  text "X" at 329.094,98.237 h1.52
  text "BOTTOM" at 332.091,98.237 h1.52
  text "SILKSCREEN COLOR:" at 291.812,94.295 h1.52
  text "X" at 316.115,94.295 h1.52
  text "WHITE" at 319.112,94.295 h1.52
  text "OTHER" at 332.091,94.295 h1.52
  text "X" at 319.442,90.652 h1.52
  text "GREEN" at 322.439,90.652 h1.52
  text "OTHER" at 338.136,90.652 h1.52
  text "SOLDER RESIST COLOR:" at 291.812,90.477 h1.52
  text "X" at 319.442,86.734 h1.52
  text "MATTE" at 322.439,86.734 h1.52
  text "SEMI-GLOSS" at 338.125,86.717 h1.52
  text "IMMERSION GOLD (ENIG)" at 314.819,82.345 h1.52
  text "ENEPIG" at 348.793,82.162 h1.52
  text "SURFACE FINISH:" at 287.87,82.136 h1.52
  text "X" at 310.298,82.136 h1.52
  text "IMM. TIN/SILVER OR EQUIV" at 296.24,78.649 h1.52
  text "OTHER" at 332.599,78.549 h1.52
  text "ARRAY/PANEL:" at 287.87,74.602 h1.52
  text "CUT AND TRIM PER M1 BOARD OUTLINE" at 314.819,74.393 h1.52
  text "N.C. ROUTE" at 314.819,70.94 h1.52
  text "X" at 332.295,70.94 h1.52
  text "V. SCORE" at 336.816,70.94 h1.52
  text "CERTIFICATION:" at 287.87,67.66 h1.52
  text "MATERIALS AND WORKMANSHIP FOR ALL PCBS" at 306.285,67.66 h1.52
  text "TO MEET OR EXCEED THE REQUIREMENTS OF:" at 306.285,65.271 h1.52
  text "X" at 297.078,62.003 h1.52
  text "ANSI IPC-A-600F CLASS ->" at 300.329,62.003 h1.52
  text "X" at 342.188,62.003 h1.52
  text "2" at 344.982,62.003 h1.52
  text "1" at 336.981,61.965 h1.52
  text "3" at 353.973,61.965 h1.52
  text "X" at 317.702,58.252 h1.52
  text "RoHS" at 320.953,58.252 h1.52
  text "OTHER" at 337.321,58.252 h1.52
  text "PER ORDER" at 347.407,58.252 h1.52
  text "ALL BOARDS MUST MEET OR EXCEED UL94-V0 REQUIREMENTS." at 288.569,54.345 h1.52
  text "PCB MUST BEAR THE UL94V-0 UL REGISTERED MATERIAL ID NUMBER" at 288.569,51.397 h1.52
  text "ADDITIONAL REQUIREMENTS:" at 287.87,47.094 h1.52
  text "MICROSECTION:" at 289.769,44.373 h1.52
  text "YES" at 312.775,44.373 h1.52
  text "REQUIRED" at 334.657,40.707 h1.52
  text "BARE BOARD ELEC. TEST:" at 289.769,40.634 h1.52
  text "NONE" at 322.935,40.634 h1.52
  text "X" at 331.66,40.634 h1.52
  text "PER ORDER" at 349.693,40.634 h1.52
  text "XX MIL VIAS REQUIRE NON-CONDUCTIVE FILL AND PLANARIZE" at 294.04,35.428 h1.5
  text "XX MIL VIAS REQUIRE CONDUCTIVE FILL AND PLANARIZE" at 294.243,32.787 h1.52
  text "OUTER XX MIL TRACES REQUIRE 50 OHM SINGLE-ENDED IMPEDANCE" at 294.218,28.637 h1.47
  text "LAYER 2 & 3 (INNER LAYERS) XX MIL WIDE, XX MIL SPACE / TRACES REQUIRE 100 OHM DIFFERENTIAL IMPEDANCE" at 294.015,22.65 h1.52
  text ".Layer_Name" at 14.656,-21.806 h1.52
M11 Gerber Information:
  lines w0.254: -7.417,-23.626 160.223,-23.626 ; -7.417,-18.462 160.274,-18.462 ; -7.417,-13.297 -7.417,-28.791 94.31,-28.791 160.274,-28.791 160.274,-13.297 -7.404,-13.297 -7.404,-28.791 32.614,-28.791 ; 55.194,-28.791 55.194,-13.297 ; 87.376,-18.462 87.376,-13.297 ; 108.712,-18.462 108.712,-13.297 ; 124.511,-28.956 124.511,-23.804
  text "ALL ARTWORK VIEWED FROM TOP SIDE" at -5.804,-16.654 h1.52
  text "BOARD #:" at 57.099,-16.654 h1.52
  text ".PRJ_Number" at 70.955,-16.654 h1.52
  text "REV:" at 92.405,-16.654 h1.52
  text ".PCB_Rev" at 99.809,-16.654 h1.52
  text "SVN REV:" at 113.69,-16.654 h1.52
  text ".VersionControl_RevNumber" at 126.543,-16.654 h1.52
  text "LAYER NAME =" at -5.804,-21.806 h1.52
  text "TID #:" at 57.099,-21.819 h1.52
  text ".TID" at 70.955,-21.819 h1.52
  text "PLOT NAME =" at -5.804,-27.034 h1.52
  text ".plot_File_Name" at 14.656,-27.034 h1.52
  text "GENERATED    :" at 57.15,-27.034 h1.52
  text ".Print_Date" at 79.235,-27.034 h1.52
  text ".Print_Time" at 97.752,-27.034 h1.52
  text "TEXAS INSTRUMENTS" at 129.87,-27.034 h1.52
M12 Stackup:
  drawing of 399 lines, arcs and shapes, not listed
  text "Layer" at 249.119,192.595 h1.52
  text "Name" at 259.531,192.595 h1.52
  text "Material" at 283.147,192.595 h1.52
  text "Thickness" at 304.985,192.595 h1.52
  text "Constant" at 321.49,192.595 h1.52
  text "Board Layer Stack" at 335.965,192.595 h1.52
  text "Top Overlay" at 259.531,189.547 h1.52
  text "Top Solder" at 259.531,186.499 h1.52
  text "Solder Resist" at 283.147,186.499 h1.52
  text "0.40mil" at 304.985,186.499 h1.52
  text "3.5" at 321.49,186.499 h1.52
  text "1" at 249.119,183.451 h1.52
  text "Top Layer" at 259.531,183.451 h1.52
  text "Copper" at 283.147,183.451 h1.52
  text "2.76mil" at 304.985,183.451 h1.52
  text "Dielectric 1" at 259.531,180.403 h1.52
  text "PP-006" at 283.147,180.403 h1.52
  text "9.13mil" at 304.985,180.403 h1.52
  text "4.1" at 321.49,180.403 h1.52
  text "2" at 249.119,177.356 h1.52
  text "Layer 2" at 259.531,177.356 h1.52
  text "Copper" at 283.147,177.356 h1.52
  text "1.38mil" at 304.985,177.356 h1.52
  text "Dielectric 2" at 259.531,174.308 h1.52
  text "PP-006" at 283.147,174.308 h1.52
  text "14.17mil" at 304.985,174.308 h1.52
  text "4.1" at 321.49,174.308 h1.52
  text "3" at 249.119,171.26 h1.52
  text "Layer 3" at 259.531,171.26 h1.52
  text "Copper" at 283.147,171.26 h1.52
  text "1.38mil" at 304.985,171.26 h1.52
  text "Dielectric 3" at 259.531,168.212 h1.52
  text "FR-4" at 283.147,168.212 h1.52
  text "11.65mil" at 304.985,168.212 h1.52
  text "4.8" at 321.49,168.212 h1.52
  text "4" at 249.119,165.163 h1.52
  text "Layer 4" at 259.531,165.163 h1.52
  text "Copper" at 283.147,165.163 h1.52
  text "1.38mil" at 304.985,165.163 h1.52
  text "Dielectric 4" at 259.531,162.115 h1.52
  text "PP-006" at 283.147,162.115 h1.52
  text "14.17mil" at 304.985,162.115 h1.52
  text "4.1" at 321.49,162.115 h1.52
  text "5" at 249.119,159.067 h1.52
  text "Layer 5" at 259.531,159.067 h1.52
  text "Copper" at 283.147,159.067 h1.52
  text "1.38mil" at 304.985,159.067 h1.52
  text "Dielectric 5" at 259.531,156.019 h1.52
  text "PP-006" at 283.147,156.019 h1.52
  text "9.13mil" at 304.985,156.019 h1.52
  text "4.1" at 321.49,156.019 h1.52
  text "6" at 249.119,152.971 h1.52
  text "Bottom Layer" at 259.531,152.971 h1.52
  text "Copper" at 283.147,152.971 h1.52
  text "2.76mil" at 304.985,152.971 h1.52
  text "Bottom Solder" at 259.531,149.923 h1.52
  text "Solder Resist" at 283.147,149.923 h1.52
  text "0.40mil" at 304.985,149.923 h1.52
  text "3.5" at 321.49,149.923 h1.52
  text "Bottom Overlay" at 259.531,146.875 h1.52
  text ".Layer_Name" at 14.656,-21.806 h1.52
M13 Component Bodies Top:
  text ".Layer_Name" at 14.656,-21.806 h1.52
M14 Component Bodies Bottom:
  text ".Layer_Name" at 14.656,-21.806 h1.52
M15 Courtyards Top:
  text ".Layer_Name" at 14.656,-21.806 h1.52
M16 Courtyards Bottom:
  text ".Layer_Name" at 14.656,-21.806 h1.52
Drill Drawing:
  circle w0.254: c136.241,71.984 r0.703
  lines w0.254: 135.538,74.444 136.944,74.444 136.944,75.849 135.538,75.849 135.538,74.444 ; 135.538,77.606 136.241,77.957 136.944,77.606 136.593,78.309 136.944,79.011 136.241,78.66 135.538,79.011 135.89,78.309 135.538,77.606 ; 135.538,81.12 135.89,81.12 135.89,80.768 136.593,80.768 136.593,81.12 136.944,81.12 136.944,81.822 136.593,81.822 136.593,82.174 135.89,82.174 135.89,81.822 135.538,81.822 135.538,81.12 ; 135.538,84.282 135.89,84.282 136.241,83.93 136.593,84.282 136.944,84.282 136.593,84.633 136.944,84.985 136.593,84.985 136.241,85.336 135.89,84.985 135.538,84.985 135.89,84.633 135.538,84.282
  lines w0.305: 134.264,70.333 216.362,70.333 ; 134.264,86.144 216.362,86.144 ; 142.85,67.17 142.85,89.306 ; 151.287,67.17 151.287,89.306 ; 167.453,67.17 167.453,89.306 ; 174.037,67.17 174.037,89.306 ; 183.568,67.17 183.568,89.306 ; 201.972,67.17 201.972,89.306 ; 134.264,67.17 216.362,67.17 216.362,89.306 134.264,89.306 134.264,67.17
  text "Symbol" at 136.162,87.093 h1.83
  text "Quantity" at 143.799,87.093 h1.83
  text "Finished Hole Size" at 152.235,87.093 h1.83
  text "Plated" at 168.402,87.093 h1.83
  text "Hole Type" at 174.986,87.093 h1.83
  text "Drill Layer Pair" at 184.517,87.093 h1.83
  text "Hole Tolerance" at 202.92,87.093 h1.83
  text "137" at 143.799,83.93 h1.52
  text "11.81mil (0.300mm)" at 152.235,83.93 h1.52
  text "PTH" at 168.402,83.93 h1.52
  text "Round" at 174.986,83.93 h1.52
  text "Top Layer - Bottom Layer" at 184.517,83.93 h1.52
  text "1" at 143.799,80.768 h1.52
  text "15.75mil (0.400mm)" at 152.235,80.768 h1.52
  text "PTH" at 168.402,80.768 h1.52
  text "Round" at 174.986,80.768 h1.52
  text "Top Layer - Bottom Layer" at 184.517,80.768 h1.52
  text "74" at 143.799,77.606 h1.52
  text "19.69mil (0.500mm)" at 152.235,77.606 h1.52
  text "PTH" at 168.402,77.606 h1.52
  text "Round" at 174.986,77.606 h1.52
  text "Top Layer - Bottom Layer" at 184.517,77.606 h1.52
  text "5" at 143.799,74.444 h1.52
  text "43.00mil (1.092mm)" at 152.235,74.444 h1.52
  text "PTH" at 168.402,74.444 h1.52
  text "Round" at 174.986,74.444 h1.52
  text "Top Layer - Bottom Layer" at 184.517,74.444 h1.52
  text "2" at 143.799,71.281 h1.52
  text "94.00mil (2.388mm)" at 152.235,71.281 h1.52
  text "PTH" at 168.402,71.281 h1.52
  text "Round" at 174.986,71.281 h1.52
  text "Top Layer - Bottom Layer" at 184.517,71.281 h1.52
  text "219 Total" at 143.799,68.119 h1.52
  text ".Layer_Name" at 14.656,-21.806 h1.52
M17 Embedded Cavity:
  text ".Layer_Name" at 14.656,-21.806 h1.52
M18 Embedded Assembly:
  text ".Layer_Name" at 14.656,-21.806 h1.52
M19 Embedded Keepout:
  text ".Layer_Name" at 14.656,-21.806 h1.52

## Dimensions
3.778,44.46 to 88.011,41.783 on Top Overlay
3.778,1.27 to 3.778,44.46 on Top Overlay
0,-10.16 to 25.4,-10.16 on M2 Board Dimensions
0,0 to 0,46.99 on M2 Board Dimensions
0,0 to 88.9,0 on M2 Board Dimensions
